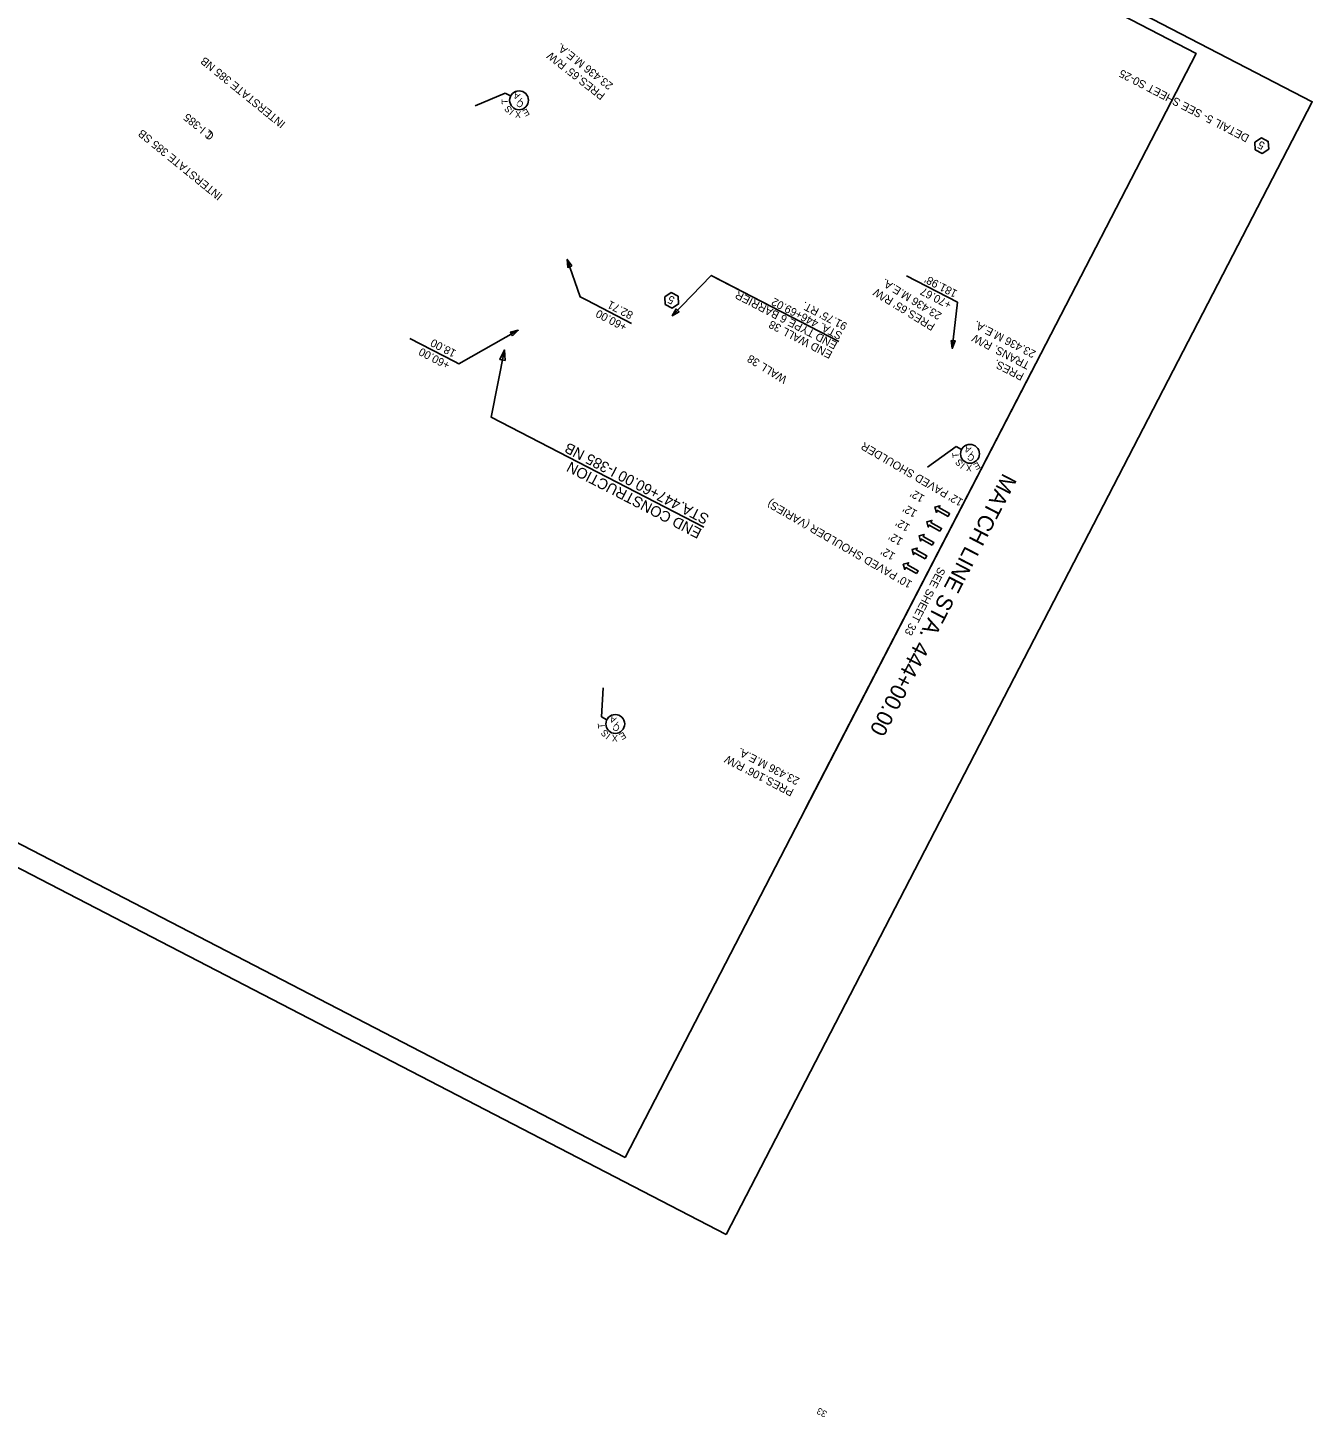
# Model space of a CAD drawing. Extents: x 1605035 to 1606962, y 1094993 to 1096933.
# Drawn here: x 1605999 to 1606962, y 1094993 to 1096034 of the extents above; entities that cross this region are included whole.
import ezdxf

# ---------------------------------------------------------------- set-up
doc = ezdxf.new("R2010")
doc.units = 0
for name, color, linetype in [('RD_DTM_Void', 7, 'Continuous'), ('RD_EX_Bldg', 7, 'Continuous'), ('RD_EX_DV_TX_Prop', 7, 'Continuous'), ('RD_EX_GuardRail', 7, 'Continuous'), ('RD_EX_H2O', 7, 'Continuous'), ('RD_EX_RW', 7, 'Continuous'), ('RD_HC_Data_Rel', 7, 'Continuous'), ('RD_SHT_DR_TX_FINAL', 7, 'Continuous'), ('RD_SHT_UT_TX_PREL', 7, 'Continuous')]:
    doc.layers.add(name, color=color, linetype=linetype)

msp = doc.modelspace()

# ---------------------------------------------------------------- linework, layer by layer
at = {"layer": 'RD_EX_Bldg'}
msp.add_lwpolyline([(1606446.6, 1095187.4), (1605250.2, 1095806.8), (1605262.7, 1095830.9), (1605127.4, 1095901.8), (1605543.2, 1096704.9), (1606875.2, 1096015.2)], close=True, dxfattribs=at)
msp.add_lwpolyline([(1606446.6, 1095187.4), (1605250.2, 1095806.8), (1605262.7, 1095830.9), (1605127.4, 1095901.8), (1605543.2, 1096704.9), (1606875.2, 1096015.2)], close=True, dxfattribs=at)
at = {"layer": 'RD_EX_DV_TX_Prop'}
for points in [[(1606689, 1095668.1), (1606690.1, 1095670.2), (1606682.1, 1095674.7), (1606682.9, 1095676.1), (1606679.1, 1095675), (1606680.2, 1095671.1), (1606681, 1095672.6)], [(1606682.9, 1095657), (1606684.1, 1095659.1), (1606676.1, 1095663.6), (1606676.9, 1095665.1), (1606673.1, 1095664), (1606674.1, 1095660.1), (1606674.9, 1095661.5)], [(1606677, 1095646.5), (1606678.2, 1095648.6), (1606670.2, 1095653.1), (1606671, 1095654.5), (1606667.2, 1095653.4), (1606668.2, 1095649.6), (1606669, 1095651)], [(1606671.9, 1095636.3), (1606673.1, 1095638.4), (1606665.1, 1095642.9), (1606665.9, 1095644.3), (1606662, 1095643.2), (1606663.1, 1095639.4), (1606663.9, 1095640.8)], [(1606665.3, 1095625.3), (1606666.5, 1095627.3), (1606658.5, 1095631.8), (1606659.3, 1095633.3), (1606655.4, 1095632.2), (1606656.5, 1095628.3), (1606657.3, 1095629.7)]]:
    msp.add_lwpolyline(points, close=True, dxfattribs=at)
at = {"layer": 'RD_EX_GuardRail'}
msp.add_lwpolyline([(1606522.5, 1095129.6), (1605034.9, 1095899.6), (1605474.6, 1096749), (1606962.2, 1095979)], close=True, dxfattribs=at)
at = {"layer": 'RD_EX_RW'}
msp.add_lwpolyline([(1606657.7, 1095848.5), (1606696, 1095828.7), (1606692.1, 1095794.1)], dxfattribs=at)
msp.add_lwpolyline([(1606691.2, 1095800.1), (1606692.1, 1095794.1), (1606694.3, 1095799.7)], close=True, dxfattribs=at)
at = {"layer": 'RD_HC_Data_Rel'}
for p, q in [((1606356.7, 1095985.5), (1606334.1, 1095976)), ((1606360.8, 1095983.4), (1606356.7, 1095985.5)), ((1606695, 1095720.4), (1606673.6, 1095704.9)), ((1606699.1, 1095718.2), (1606695, 1095720.4)), ((1606428.9, 1095517.7), (1606430.1, 1095539.5)), ((1606433, 1095515.6), (1606428.9, 1095517.7))]:
    msp.add_line(p, q, dxfattribs=at)
for centre in [(1606367.1, 1095980.1), (1606705.4, 1095715), (1606439.3, 1095512.4)]:
    msp.add_circle(centre, 7.08, dxfattribs=at)
at = {"layer": 'RD_SHT_DR_TX_FINAL'}
msp.add_line((1606751.8, 1095776.9), (1606581.4, 1095447.9), dxfattribs=at)
at = {"layer": 'RD_SHT_UT_TX_PREL'}
for p, q in [((1606513.7, 1095847.5), (1606607, 1095799.2)), ((1606417.9, 1095830.2), (1606451.4, 1095812.8)), ((1606285.1, 1095801.6), (1606318.6, 1095784.2))]:
    msp.add_line(p, q, dxfattribs=at)
for points in [[(1606919.1, 1095948.8), (1606919.4, 1095943), (1606924.6, 1095940.3), (1606929.5, 1095943.5), (1606929.2, 1095949.3), (1606924, 1095951.9)], [(1606406.7, 1095855.9), (1606403.3, 1095860.8), (1606403.7, 1095854.8)], [(1606476.4, 1095832.8), (1606476.7, 1095827), (1606481.9, 1095824.3), (1606486.8, 1095827.4), (1606486.5, 1095833.2), (1606481.3, 1095835.9)], [(1606484.9, 1095823.8), (1606482, 1095818.5), (1606487.2, 1095821.6)], [(1606362.2, 1095803.4), (1606366.5, 1095807.7), (1606360.6, 1095806.2)], [(1606356.7, 1095784.9), (1606356.2, 1095792.9), (1606352.7, 1095785.7)]]:
    msp.add_lwpolyline(points, close=True, dxfattribs=at)
for points in [[(1606417.9, 1095830.2), (1606413, 1095832.7), (1606403.3, 1095860.8)], [(1606607, 1095799.2), (1606511.3, 1095848.8), (1606482, 1095818.5)], [(1606318.6, 1095784.2), (1606321.9, 1095782.5), (1606366.5, 1095807.7)], [(1606505.8, 1095659.9), (1606346.3, 1095742.4), (1606356.2, 1095792.9)]]:
    msp.add_lwpolyline(points, dxfattribs=at)

# ---------------------------------------------------------------- texts
at = {"layer": 'RD_DTM_Void'}
for s, p in [('INTERSTATE 385 NB', (1606192.4, 1095963.3)), ('C I-385', (1606138.9, 1095954.2)), ('INTERSTATE 385 SB', (1606145.2, 1095909.2)), ('L', (1606137.7, 1095955.8))]:
    msp.add_text(s, height=6, rotation=140.8375, dxfattribs=at).set_placement(p)
at = {"layer": 'RD_EX_H2O'}
msp.add_text('33', height=5, rotation=152.6268, dxfattribs=at).set_placement((1606598.7, 1094996.5))
at = {"layer": 'RD_EX_RW'}
for s, rotation, p in [('23.436 M.E.A.', 141.8214, (1606438.1, 1095992.1)), ("PRES.65' R/W", 141.8214, (1606432.2, 1095984.6)), ('23.436 M.E.A.', 148.3366, (1606684.8, 1095820.1)), ("181.98'", 152.6341, (1606696.5, 1095837.1)), ("PRES.65' R/W", 148.3366, (1606679.8, 1095812)), ('+70.67', 152.6341, (1606692.2, 1095828.7)), ('23.436 M.E.A.', 152.6268, (1606755.3, 1095791.8)), ('TRANS. R/W ', 152.6268, (1606750.9, 1095783.3)), ('PRES.', 152.6268, (1606746.5, 1095774.9)), ('23.436 M.E.A.', 152.6268, (1606578.1, 1095471.5)), ("PRES.106' R/W", 152.6268, (1606573.8, 1095463.1))]:
    msp.add_text(s, height=6, rotation=rotation, dxfattribs=at).set_placement(p)
at = {"layer": 'RD_HC_Data_Rel'}
for s, rotation, p in [('T', 93.7321, (1606359.2, 1095977.3)), ('A', 152.6309, (1606368.4, 1095984.7)), ('/', 152.6309, (1606369.5, 1095981.7)), ('S', 128.8935, (1606362.3, 1095973.2)), ('I', 140.614, (1606363.8, 1095972.4)), ('X', 175.7755, (1606368.8, 1095971.9)), ('C', 152.6309, (1606371.1, 1095978.5)), ('E', 209.2626, (1606373.1, 1095974.2)), ('A', 152.6309, (1606706.7, 1095719.5)), ('T', 93.7321, (1606697.4, 1095712.1)), ('S', 128.8935, (1606700.6, 1095708.1)), ('C', 152.6309, (1606709.4, 1095713.3)), ('/', 152.6309, (1606707.8, 1095716.6)), ('I', 140.614, (1606702.1, 1095707.2)), ('X', 175.7755, (1606707.1, 1095706.8)), ('E', 209.2626, (1606711.4, 1095709.1)), ('T', 95.6842, (1606431.5, 1095509.2)), ('A', 152.6309, (1606440.6, 1095516.9)), ('C', 152.6309, (1606443.3, 1095510.7)), ('/', 152.6309, (1606441.7, 1095513.9)), ('S', 130.8457, (1606434.7, 1095505.3)), ('I', 142.5662, (1606436.2, 1095504.5)), ('X', 177.7276, (1606441.3, 1095504.2)), ('E', 211.2148, (1606445.5, 1095506.7))]:
    msp.add_text(s, height=5, rotation=rotation, dxfattribs=at).set_placement(p)
at = {"layer": 'RD_SHT_DR_TX_FINAL'}
for s, height, p in [('MATCH LINE STA. 444+00.00', 12, (1606730.3, 1095701.1)), ('SEE SHEET 33', 6, (1606682, 1095630.6))]:
    msp.add_text(s, height=height, rotation=242.5719, dxfattribs=at).set_placement(p)
at = {"layer": 'RD_SHT_UT_TX_PREL'}
for s, height, rotation, p in [('DETAIL 5- SEE SHEET S0-25', 6, 152.6341, (1606915.5, 1095953.7)), ('5', 6, 152.6341, (1606927.2, 1095948)), ('END TYPE 6 BARRIER', 6, 152.6325, (1606606.5, 1095798.4)), ('82.71', 6, 152.6268, (1606453.3, 1095820.9)), ('5', 6, 152.6341, (1606484.5, 1095832)), ('STA. 446+69.02', 6, 152.6325, (1606610.2, 1095805.5)), ("91.75' RT.", 6, 152.6325, (1606613.9, 1095812.6)), ('+60.00', 6, 152.6268, (1606448.7, 1095812)), ('END WALL 38', 6, 152.6325, (1606602.8, 1095791.3)), ('+60.00', 6, 152.6268, (1606315.9, 1095783.4)), ('18.00', 6, 152.6268, (1606320.5, 1095792.3)), ('WALL 38', 6, 148.4679, (1606568.8, 1095772.4)), ('STA.447+60.00 I-385 NB', 8, 152.6341, (1606510.4, 1095668.7)), ("12' PAVED SHOULDER", 6, 149.7507, (1606700.8, 1095680.4)), ('END CONSTRUCTION', 8, 152.6341, (1606504.9, 1095658.1)), ("10' PAVED SHOULDER (VARIES)", 6, 149.8984, (1606662.6, 1095618.9)), ("12'", 6, 149.8476, (1606671.9, 1095683.3)), ("12'", 6, 149.8476, (1606666.4, 1095672)), ("12'", 6, 149.8476, (1606661, 1095661.4)), ("12'", 6, 149.8476, (1606655.7, 1095651)), ("12'", 6, 149.8476, (1606649.9, 1095639.9))]:
    msp.add_text(s, height=height, rotation=rotation, dxfattribs=at).set_placement(p)

doc.saveas('drawing.dxf')
